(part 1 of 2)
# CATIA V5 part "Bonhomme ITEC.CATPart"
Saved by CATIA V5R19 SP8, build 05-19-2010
Part number: Bonhomme STI 2D
Revision: ANY
Definition: UNKNOWN
Nomenclature: Bonhomme STI 2D
Source: Unknown
Bounding box of the stored display mesh (mm): x -9.149 to 9.622, y -25.063 to 17.35, z -81.288 to -22.199
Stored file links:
  D:\Documents\1_Travail\3 -  Supports d'étude\Bonhomme_ITEC\Activités pédagogiques_Bonhomme ITEC\Activité_4-9.2h_Conception_moule\Activité 4-9.2h_Conception moule silicone\Bonhomme ITEC.CATPart
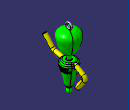
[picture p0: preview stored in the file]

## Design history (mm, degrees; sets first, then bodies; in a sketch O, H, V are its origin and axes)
Set1 "Gravure"
  Sketch1 on yz-plane, origin (0, 0, 0), H (0, 1, 0), V (0, 0, 1)
    polyline C1
    polyline C2
    polyline C3
    polyline C4
    polyline C5
    polyline C6
    polyline C7
    polyline C8
    polyline C9
    polyline C10
  Sketch2 on yz-plane, origin (0, 0, 0), H (0, 1, 0), V (0, 0, 1)
    polyline C1
    polyline C2
    polyline C3
    polyline C4
    polyline C5
    polyline C6
    polyline C7
    polyline C8
    polyline C9
    polyline C10
  Sketch3 on yz-plane, origin (0, 0, 0), H (0, 1, 0), V (0, 0, 1)
    point P1 (-1.9889, -61.7805)
    construction line L1 through (13.4261, 61.6) direction (1, 0)
    construction line L2 through (13.4261, 61.6) direction (0, 1)
    polyline C1
    polyline C2
    polyline C3
    polyline C4
    polyline C5
    polyline C6
    polyline C7
    polyline C8
    polyline C9
    polyline C10
    polyline C11
    polyline C12
    polyline C13
    polyline C14
    polyline C15
    polyline C16
Body1 "Corps" (main body)
  Sketch4 on yz-plane, origin (0, 0, 0), H (0, 1, 0), V (0, 0, 1)
    point P2 (0, -40.025)
    frozenspline C1
    axis line L1 (0, 0) -> (0, -40.025)
    vertical: L1 V
  Shaft1: profile Sketch4, axis Sketch4.L1, angle 360
  Plane1: type OffsetPt, RefPlane xy-plane, RefPoint Sketch4.P2
  Sketch5 on Plane1, origin (0, 0, -40.025), H (1, 0, 0), V (0, 1, 0)
    circle A1 centre (0, 0) radius 4
    radius A1 = 4
  Pad1: profile Sketch5, direction (0, 0, -1), length 10, mirrored extent
  Fillet1: radius 3, on edge [face of Shaft1 from Sketch4.C1 | face of Pad1 from Sketch5.A1]
  Sketch6 on yz-plane, origin (0, 0, 0), H (0, 1, 0), V (0, 0, 1)
    point P1 (0, -50.025)
    line L1 (0, -50.025) -> (11, -50.025)
    line L2 (11, -50.025) -> (15, -54.525)
    point P3 (15, -54.525)
    line L3 (15, -54.525) -> (5.5, -93.6361)
    point P4 (5.5, -93.6361)
    line L4 (5.5, -93.6361) -> (0, -98.525)
    point P5 (0, -98.525)
    axis line L5 (0, -50.025) -> (0, -98.525)
    point P6 (0, -98.525)
    reference intersected line E1 (4, -50.025) -> (-4, -50.025) from end face of Pad1
    length L1 = 11
    distance L5 P3 = 15
    distance P4 L5 = 5.5
    distance P5 L1 = 48.5
    distance P3 L1 = 4.5
    coincidence: P1 V, P5 V, P6 L4, L1 E1
    horizontal: L1 H
    vertical: L5 V
    perpendicularity: L2 L4
  Shaft2: profile Sketch6, axis Sketch6.L5, angle 360
  Sketch7 on yz-plane, origin (0, 0, 0), H (0, 1, 0), V (0, 0, 1)
    arc A1 centre (0, -102.025) radius 4.5 from (0, -106.525) to (0, -97.525) ccw
    point P1 (0, -102.025)
    reference projected point E1 (0, -98.525) from Sketch6.P5
    line L1 (0, -97.525) -> (0, -106.525)
    radius A1 = 4.5
    distance A1 E1 = 1
    coincidence: P1 V, L1 P1
    vertical: L1 V
  Shaft3: profile Sketch7, axis Sketch7.L1, angle 360
  Fillet2: radius 3, on edge [face of Shaft2 from Sketch6.L3 | face of Shaft2 from Sketch6.L4]; edge [face of Shaft2 from Sketch6.L2 | face of Shaft2 from Sketch6.L3]; edge [face of Shaft2 from Sketch6.L1 | face of Shaft2 from Sketch6.L2]
  Fillet3: radius 0.75, on face of Shaft2 from Sketch6.L4
  Sketch8 on zx-plane, origin (0, 0, 0), H (-1, 0, 0), V (0, 0, 1)
    circle A1 centre (0, -54.4777) radius 4
    point P1 (0, -54.4777)
    radius A1 = 4
    coincidence: P1 V
  Sketch9 on yz-plane, origin (0, 0, 0), H (0, 1, 0), V (0, 0, 1)
    point P1 (0, -54.525)
    line L1 (0, -54.525) -> (-10.5, -54.525)
    line L2 (-10.5, -54.525) -> (-27.5165, -50.4397)
    line L3 (-32.8425, -47.1439) -> (-47.3052, -29.9079)
    arc A1 centre (-25.182, -40.716) radius 10 from (-32.8425, -47.1439) to (-27.5165, -50.4397) ccw
    reference projected line E1 through (0, 0) direction (0, 1) from axis of face of Pad1 from Sketch5.A1
    reference projected point E2 (15, -54.525) from vertex [element of Sketch6 | element of Sketch6]
    line L4 (0, -54.525) -> (10.5, -54.525)
    point P7 (11.8397, -54.525)
    line L5 (13, -55.1949) -> (28.1554, -63.9449)
    arc A2 centre (10.5, -59.525) radius 5 from (10.5, -54.525) to (13, -55.1949) cw
    point P8 (32.8809, -66.6731)
    line L6 (29.7512, -71.1429) -> (16.6737, -89.8195)
    arc A3 centre (25.6554, -68.275) radius 5 from (29.7512, -71.1429) to (28.1554, -63.9449) ccw
    point P9 (0, -54.525)
    radius A1 = 10
    length L1 = 10.5
    angle L2 L1 = 13.5
    angle L1 L3 = 50
    length L2 = 17.5
    length L3 = 22.5
    radius A2 = 5
    radius A3 = 5
    angle L5 L6 = 85
    length L4 = 10.5
    length L5 = 17.5
    length L6 = 22.8
    angle L5 L4 = 30
    horizontal: L1 H, L4 H
    tangency: A1 L3, A1 L2, A2 L4, A2 L5, A3 L6, A3 L5
    coincidence: P1 E1, L1 E2, L4 P7, L5 P7, L6 P8, L5 P8, P9 P1
  Rib1: profile Sketch8, centre curve Sketch9
  Fillet4: radius 0.5, on edge [face of Rib1 | face of Rib1] (x2)
  Sketch10 on yz-plane, origin (0, 0, 0), H (0, 1, 0), V (0, 0, 1)
    offset curve E1 from Sketch4.C1
    offset curve E2 from Sketch4.C1
    point P3 (-5.2108, -35)
    line L1 (-5.2108, -35) -> (0, -35)
    point P4 (0, -35)
    line L2 (0, -35) -> (0, -7)
    line L3 (0, -7) -> (-12.8767, -7)
    point P6 (-13.768, -7)
    point P7 (-13.768, -7)
    arc A1 centre (-12.8767, -9) radius 2 from (-12.8767, -7) to (-14.4944, -7.824) ccw
    distance L3 L1 = 28
    distance L3 H = 7
    radius A1 = 2
    coincidence: P3 E1, P4 V, L3 P6, E1 P7, L3 P7, E1 P6
    horizontal: L1 H, L3 H
    vertical: L2 V
    tangency: A1 L3, A1 E1
  Pocket1: profile Sketch10, direction (-1, 0, 0), through (limit type 3)
  Mirror1: of Pocket1, about face of Pocket1 from Sketch10.L2
  Sketch11 on yz-plane, origin (0, 0, 0), H (0, 1, 0), V (0, 0, 1)
    offset curve E1 from Sketch4.C1
    offset curve E2 from Sketch4.C1
    axis line L1 (0, -40.2105) -> (0, 0.6005)
    point P3 (0, -40.2105)
    point P5 (0, -38.5215)
    line L2 (-0.503, -1.4132) -> (0, -1.0375)
    point P6 (0, -1.0375)
    coincidence: P3 V, L1 P5, P6 L1
    vertical: L1 V
  Shaft4: profile Sketch11, axis Sketch11.L1, angle 180
  Sketch12 on yz-plane, origin (0, 0, 0), H (0, 1, 0), V (0, 0, 1)
    point P1 (5, -23.5)
    ellipse A1 centre (5, -23.5) semi-axes 4.5, 2.5 rotation 258.716
    reference intersected line E1 through (0, 0) direction (0, 1) from zx-plane
    reference intersected line E2 (0, -35) -> (-5.2108, -35) from face of Mirror1
    "Radius" A1 = 4.5
    "Radius" A1 = 2.5
    distance P1 E1 = 5
    distance E2 P1 = 11.5
  Pad2: profile Sketch12, direction (-1, 0, 0), up to face of Shaft4 from Sketch11.E2, offset 1.5
  Mirror2: of Pad2, about zx-plane
  Sketch13 on zx-plane, origin (0, 0, 0), H (-1, 0, 0), V (0, 0, 1)
    arc A1 centre (14, -30.9467) radius 3 from (16.7513, -32.1427) to (15.2913, -28.2389) ccw
    point P1 (14, -30.9467)
    line L1 (15.2913, -28.2389) -> (8.1264, -24.8223)
    line L2 (8.1264, -24.8223) -> (6.7159, -27.7804)
    reference projected line E1 through (0, 0) direction (0, 1) from axis of face of Pad1 from Sketch5.A1
    reference projected line E2 (-6.0494, -38.9467) -> (6.0494, -38.9467) from edge [face of Fillet1 | face of Shaft1 from Sketch4.C1]
    axis line L3 (20.0017, -33.5557) -> (2.8816, -26.1136)
    point P6 (16.7513, -32.1427)
    point P7 (6.7159, -27.7804)
    radius A1 = 3
    distance P1 E1 = 14
    distance E2 P1 = 8
    angle L3 L1 = 2
    tangency: L1 A1
    perpendicularity: L2 L1
    coincidence: L3 P1, L3 P6, L3 P7
  Shaft5: profile Sketch13, axis Sketch13.L3, angle 360
  Fillet5: radius 0.5, on face of Mirror2; end face of Pad2
  Fillet6: radius 0.75, on edge [face of Shaft2 from Sketch6.L2 | face of Rib1]; edge [face of Rib1 | face of Shaft2 from Sketch6.L2]
  Fillet7: radius 0.75, on face of Shaft4 from Sketch11.E2
  Fillet8: radius 0.5, on edge [face of Shaft1 from Sketch4.C1 | face of Mirror1]
  Sketch14 on yz-plane, origin (0, 0, 0), H (0, 1, 0), V (0, 0, 1)
    line L1 (0.9195, -63.8789) -> (0.9195, -59.1378)
    line L2 (0.9195, -59.1378) -> (0.9178, -59.0657)
    line L3 (0.9178, -59.0657) -> (0.9128, -58.9974)
    line L4 (0.9128, -58.9974) -> (0.9043, -58.9327)
    line L5 (0.9043, -58.9327) -> (0.8926, -58.8718)
    line L6 (0.8926, -58.8718) -> (0.8774, -58.8145)
    line L7 (0.8774, -58.8145) -> (0.8589, -58.7609)
    line L8 (0.8589, -58.7609) -> (0.837, -58.7111)
    line L9 (0.837, -58.7111) -> (0.8118, -58.6649)
    line L10 (0.8118, -58.6649) -> (0.7832, -58.6224)
    line L11 (0.7832, -58.6224) -> (0.7512, -58.5836)
    line L12 (0.7512, -58.5836) -> (0.7165, -58.5485)
    line L13 (0.7165, -58.5485) -> (0.6799, -58.5171)
    line L14 (0.6799, -58.5171) -> (0.6413, -58.4894)
    line L15 (0.6413, -58.4894) -> (0.6008, -58.4654)
    line L16 (0.6008, -58.4654) -> (0.5582, -58.4451)
    line L17 (0.5582, -58.4451) -> (0.5138, -58.4284)
    line L18 (0.5138, -58.4284) -> (0.4673, -58.4155)
    line L19 (0.4673, -58.4155) -> (0.4188, -58.4063)
    line L20 (0.4188, -58.4063) -> (0.3684, -58.4007)
    line L21 (0.3684, -58.4007) -> (0.3161, -58.3989)
    line L22 (0.3161, -58.3989) -> (0.2621, -58.4007)
    line L23 (0.2621, -58.4007) -> (0.2102, -58.4062)
    line L24 (0.2102, -58.4062) -> (0.1605, -58.4153)
    line L25 (0.1605, -58.4153) -> (0.1128, -58.4281)
    line L26 (0.1128, -58.4281) -> (0.0672, -58.4446)
    line L27 (0.0672, -58.4446) -> (0.0237, -58.4646)
    line L28 (0.0237, -58.4646) -> (-0.0177, -58.4884)
    line L29 (-0.0177, -58.4884) -> (-0.057, -58.5158)
    line L30 (-0.057, -58.5158) -> (-0.0942, -58.5468)
    line L31 (-0.0942, -58.5468) -> (-0.1293, -58.5816)
    line L32 (-0.1293, -58.5816) -> (-0.1617, -58.62)
    line L33 (-0.1617, -58.62) -> (-0.1906, -58.6622)
    line L34 (-0.1906, -58.6622) -> (-0.2162, -58.7083)
    line L35 (-0.2162, -58.7083) -> (-0.2384, -58.7582)
    line L36 (-0.2384, -58.7582) -> (-0.2571, -58.8119)
    line L37 (-0.2571, -58.8119) -> (-0.2724, -58.8695)
    line L38 (-0.2724, -58.8695) -> (-0.2843, -58.9308)
    line L39 (-0.2843, -58.9308) -> (-0.2929, -58.996)
    line L40 (-0.2929, -58.996) -> (-0.298, -59.065)
    line L41 (-0.298, -59.065) -> (-0.2997, -59.1378)
    line L42 (-0.2997, -59.1378) -> (-0.2997, -63.8789)
    line L43 (-0.2997, -63.8789) -> (-0.298, -63.9517)
    line L44 (-0.298, -63.9517) -> (-0.2929, -64.0208)
    line L45 (-0.2929, -64.0208) -> (-0.2843, -64.086)
    line L46 (-0.2843, -64.086) -> (-0.2724, -64.1475)
    line L47 (-0.2724, -64.1475) -> (-0.2571, -64.2052)
    line L48 (-0.2571, -64.2052) -> (-0.2384, -64.2592)
    line L49 (-0.2384, -64.2592) -> (-0.2162, -64.3093)
    line L50 (-0.2162, -64.3093) -> (-0.1906, -64.3557)
    line L51 (-0.1906, -64.3557) -> (-0.1617, -64.3983)
    line L52 (-0.1617, -64.3983) -> (-0.1293, -64.4372)
    line L53 (-0.1293, -64.4372) -> (-0.0942, -64.4723)
    line L54 (-0.0942, -64.4723) -> (-0.057, -64.5037)
    line L55 (-0.057, -64.5037) -> (-0.0177, -64.5314)
    line L56 (-0.0177, -64.5314) -> (0.0237, -64.5554)
    line L57 (0.0237, -64.5554) -> (0.0672, -64.5757)
    line L58 (0.0672, -64.5757) -> (0.1128, -64.5923)
    line L59 (0.1128, -64.5923) -> (0.1605, -64.6053)
    line L60 (0.1605, -64.6053) -> (0.2102, -64.6145)
    line L61 (0.2102, -64.6145) -> (0.2621, -64.62)
    line L62 (0.2621, -64.62) -> (0.3161, -64.6219)
    line L63 (0.3161, -64.6219) -> (0.3677, -64.62)
    line L64 (0.3677, -64.62) -> (0.4175, -64.6144)
    line L65 (0.4175, -64.6144) -> (0.4654, -64.6051)
    line L66 (0.4654, -64.6051) -> (0.5115, -64.592)
    line L67 (0.5115, -64.592) -> (0.5557, -64.5752)
    line L68 (0.5557, -64.5752) -> (0.5981, -64.5546)
    line L69 (0.5981, -64.5546) -> (0.6386, -64.5304)
    line L70 (0.6386, -64.5304) -> (0.6773, -64.5024)
    line L71 (0.6773, -64.5024) -> (0.7141, -64.4706)
    line L72 (0.7141, -64.4706) -> (0.7491, -64.4351)
    line L73 (0.7491, -64.4351) -> (0.7815, -64.3959)
    line L74 (0.7815, -64.3959) -> (0.8105, -64.3531)
    line L75 (0.8105, -64.3531) -> (0.836, -64.3066)
    line L76 (0.836, -64.3066) -> (0.8582, -64.2565)
    line L77 (0.8582, -64.2565) -> (0.8769, -64.2027)
    line L78 (0.8769, -64.2027) -> (0.8922, -64.1452)
    line L79 (0.8922, -64.1452) -> (0.9042, -64.0841)
    line L80 (0.9042, -64.0841) -> (0.9127, -64.0194)
    line L81 (0.9127, -64.0194) -> (0.9178, -63.951)
    line L82 (0.9178, -63.951) -> (0.9195, -63.8789)
    line L83 (-2.8078, -62.202) -> (-2.8931, -62.124)
    line L84 (-2.8931, -62.124) -> (-2.9734, -62.0514)
    line L85 (-2.9734, -62.0514) -> (-3.0487, -61.9844)
    line L86 (-3.0487, -61.9844) -> (-3.1191, -61.9229)
    line L87 (-3.1191, -61.9229) -> (-3.1844, -61.867)
    line L88 (-3.1844, -61.867) -> (-3.2447, -61.8166)
    line L89 (-3.2447, -61.8166) -> (-3.3, -61.7718)
    line L90 (-3.3, -61.7718) -> (-3.3503, -61.7325)
    line L91 (-3.3503, -61.7325) -> (-3.3955, -61.6987)
    line L92 (-3.3955, -61.6987) -> (-3.4358, -61.6705)
    line L93 (-3.4358, -61.6705) -> (-3.502, -61.6228)
    line L94 (-3.502, -61.6228) -> (-3.5659, -61.5752)
    line L95 (-3.5659, -61.5752) -> (-3.6276, -61.5274)
    line L96 (-3.6276, -61.5274) -> (-3.687, -61.4797)
    line L97 (-3.687, -61.4797) -> (-3.7442, -61.4319)
    line L98 (-3.7442, -61.4319) -> (-3.7991, -61.384)
    line L99 (-3.7991, -61.384) -> (-3.8517, -61.3362)
    line L100 (-3.8517, -61.3362) -> (-3.9021, -61.2882)
    line L101 (-3.9021, -61.2882) -> (-3.9502, -61.2403)
    line L102 (-3.9502, -61.2403) -> (-3.9961, -61.1923)
    line L103 (-3.9961, -61.1923) -> (-4.0398, -61.1441)
    line L104 (-4.0398, -61.1441) -> (-4.0813, -61.0957)
    line L105 (-4.0813, -61.0957) -> (-4.1207, -61.0471)
    line L106 (-4.1207, -61.0471) -> (-4.158, -60.9982)
    line L107 (-4.158, -60.9982) -> (-4.1932, -60.949)
    line L108 (-4.1932, -60.949) -> (-4.2262, -60.8997)
    line L109 (-4.2262, -60.8997) -> (-4.257, -60.85)
    line L110 (-4.257, -60.85) -> (-4.2858, -60.8002)
    line L111 (-4.2858, -60.8002) -> (-4.3124, -60.75)
    line L112 (-4.3124, -60.75) -> (-4.3368, -60.6997)
    line L113 (-4.3368, -60.6997) -> (-4.3591, -60.6493)
    line L114 (-4.3591, -60.6493) -> (-4.3789, -60.5991)
    line L115 (-4.3789, -60.5991) -> (-4.3965, -60.5491)
    line L116 (-4.3965, -60.5491) -> (-4.4117, -60.4994)
    line L117 (-4.4117, -60.4994) -> (-4.4246, -60.4498)
    line L118 (-4.4246, -60.4498) -> (-4.4351, -60.4004)
    line L119 (-4.4351, -60.4004) -> (-4.4433, -60.3513)
    line L120 (-4.4433, -60.3513) -> (-4.4491, -60.3023)
    line L121 (-4.4491, -60.3023) -> (-4.4526, -60.2536)
    line L122 (-4.4526, -60.2536) -> (-4.4538, -60.205)
    line L123 (-4.4538, -60.205) -> (-4.4526, -60.153)
    line L124 (-4.4526, -60.153) -> (-4.4488, -60.1022)
    line L125 (-4.4488, -60.1022) -> (-4.4425, -60.0524)
    line L126 (-4.4425, -60.0524) -> (-4.4338, -60.0037)
    line L127 (-4.4338, -60.0037) -> (-4.4225, -59.9562)
    line L128 (-4.4225, -59.9562) -> (-4.4087, -59.9097)
    line L129 (-4.4087, -59.9097) -> (-4.3925, -59.8644)
    line L130 (-4.3925, -59.8644) -> (-4.3737, -59.8202)
    line L131 (-4.3737, -59.8202) -> (-4.3524, -59.777)
    line L132 (-4.3524, -59.777) -> (-4.3286, -59.735)
    line L133 (-4.3286, -59.735) -> (-4.3027, -59.6945)
    line L134 (-4.3027, -59.6945) -> (-4.2749, -59.6558)
    line L135 (-4.2749, -59.6558) -> (-4.2454, -59.619)
    line L136 (-4.2454, -59.619) -> (-4.214, -59.584)
    line L137 (-4.214, -59.584) -> (-4.1808, -59.5508)
    line L138 (-4.1808, -59.5508) -> (-4.1459, -59.5195)
    line L139 (-4.1459, -59.5195) -> (-4.1091, -59.4901)
    line L140 (-4.1091, -59.4901) -> (-4.0705, -59.4624)
    line L141 (-4.0705, -59.4624) -> (-4.0301, -59.4367)
    line L142 (-4.0301, -59.4367) -> (-3.9879, -59.4128)
    line L143 (-3.9879, -59.4128) -> (-3.9444, -59.391)
    line L144 (-3.9444, -59.391) -> (-3.9001, -59.3714)
    line L145 (-3.9001, -59.3714) -> (-3.8551, -59.3542)
    line L146 (-3.8551, -59.3542) -> (-3.8093, -59.3392)
    line L147 (-3.8093, -59.3392) -> (-3.7626, -59.3266)
    line L148 (-3.7626, -59.3266) -> (-3.7153, -59.3162)
    line L149 (-3.7153, -59.3162) -> (-3.6671, -59.3082)
    line L150 (-3.6671, -59.3082) -> (-3.6181, -59.3024)
    line L151 (-3.6181, -59.3024) -> (-3.5684, -59.299)
    line L152 (-3.5684, -59.299) -> (-3.5179, -59.2979)
    line L153 (-3.5179, -59.2979) -> (-3.4126, -59.3026)
    line L154 (-3.4126, -59.3026) -> (-3.312, -59.3167)
    line L155 (-3.312, -59.3167) -> (-3.2159, -59.3403)
    line L156 (-3.2159, -59.3403) -> (-3.1245, -59.3734)
    line L157 (-3.1245, -59.3734) -> (-3.0376, -59.4159)
    line L158 (-3.0376, -59.4159) -> (-2.9554, -59.4678)
    line L159 (-2.9554, -59.4678) -> (-2.8777, -59.5292)
    line L160 (-2.8777, -59.5292) -> (-2.8046, -59.6)
    line L161 (-2.8046, -59.6) -> (-2.7362, -59.6802)
    line L162 (-2.7362, -59.6802) -> (-2.6723, -59.7699)
    line L163 (-2.6723, -59.7699) -> (-2.6635, -59.7844)
    line L164 (-2.6635, -59.7844) -> (-2.6537, -59.8031)
    line L165 (-2.6537, -59.8031) -> (-2.6427, -59.8261)
    line L166 (-2.6427, -59.8261) -> (-2.6306, -59.8533)
    line L167 (-2.6306, -59.8533) -> (-2.6174, -59.8848)
    line L168 (-2.6174, -59.8848) -> (-2.6031, -59.9206)
    line L169 (-2.6031, -59.9206) -> (-2.5877, -59.9607)
    line L170 (-2.5877, -59.9607) -> (-2.5711, -60.005)
    line L171 (-2.5711, -60.005) -> (-2.5535, -60.0536)
    line L172 (-2.5535, -60.0536) -> (-2.5348, -60.1065)
    line L173 (-2.5348, -60.1065) -> (-2.5152, -60.1602)
    line L174 (-2.5152, -60.1602) -> (-2.4952, -60.2114)
    line L175 (-2.4952, -60.2114) -> (-2.4747, -60.2601)
    line L176 (-2.4747, -60.2601) -> (-2.4537, -60.3062)
    line L177 (-2.4537, -60.3062) -> (-2.4322, -60.3497)
    line L178 (-2.4322, -60.3497) -> (-2.4102, -60.3907)
    line L179 (-2.4102, -60.3907) -> (-2.3877, -60.4292)
    line L180 (-2.3877, -60.4292) -> (-2.3647, -60.4651)
    line L181 (-2.3647, -60.4651) -> (-2.3412, -60.4985)
    line L182 (-2.3412, -60.4985) -> (-2.3172, -60.5293)
    line L183 (-2.3172, -60.5293) -> (-2.2919, -60.5574)
    line L184 (-2.2919, -60.5574) -> (-2.2643, -60.5825)
    line L185 (-2.2643, -60.5825) -> (-2.2344, -60.6047)
    line L186 (-2.2344, -60.6047) -> (-2.2023, -60.6239)
    line L187 (-2.2023, -60.6239) -> (-2.1679, -60.6401)
    line L188 (-2.1679, -60.6401) -> (-2.1313, -60.6534)
    line L189 (-2.1313, -60.6534) -> (-2.0924, -60.6638)
    line L190 (-2.0924, -60.6638) -> (-2.0512, -60.6712)
    line L191 (-2.0512, -60.6712) -> (-2.0078, -60.6756)
    line L192 (-2.0078, -60.6756) -> (-1.9621, -60.6771)
    line L193 (-1.9621, -60.6771) -> (-1.9218, -60.6757)
    line L194 (-1.9218, -60.6757) -> (-1.8828, -60.6717)
    line L195 (-1.8828, -60.6717) -> (-1.8453, -60.6649)
    line L196 (-1.8453, -60.6649) -> (-1.8091, -60.6554)
    line L197 (-1.8091, -60.6554) -> (-1.7744, -60.6432)
    line L198 (-1.7744, -60.6432) -> (-1.741, -60.6283)
    line L199 (-1.741, -60.6283) -> (-1.709, -60.6107)
    line L200 (-1.709, -60.6107) -> (-1.6784, -60.5904)
    line L201 (-1.6784, -60.5904) -> (-1.6492, -60.5674)
    line L202 (-1.6492, -60.5674) -> (-1.6214, -60.5416)
    line L203 (-1.6214, -60.5416) -> (-1.5957, -60.5136)
    line L204 (-1.5957, -60.5136) -> (-1.5727, -60.4835)
    line L205 (-1.5727, -60.4835) -> (-1.5524, -60.4515)
    line L206 (-1.5524, -60.4515) -> (-1.5348, -60.4175)
    line L207 (-1.5348, -60.4175) -> (-1.5198, -60.3815)
    line L208 (-1.5198, -60.3815) -> (-1.5077, -60.3436)
    line L209 (-1.5077, -60.3436) -> (-1.4982, -60.3037)
    line L210 (-1.4982, -60.3037) -> (-1.4914, -60.2618)
    line L211 (-1.4914, -60.2618) -> (-1.4873, -60.218)
    line L212 (-1.4873, -60.218) -> (-1.486, -60.1722)
    line L213 (-1.486, -60.1722) -> (-1.4873, -60.1153)
    line L214 (-1.4873, -60.1153) -> (-1.4911, -60.0579)
    line L215 (-1.4911, -60.0579) -> (-1.4974, -60)
    line L216 (-1.4974, -60) -> (-1.5063, -59.9416)
    line L217 (-1.5063, -59.9416) -> (-1.5178, -59.8828)
    line L218 (-1.5178, -59.8828) -> (-1.5318, -59.8234)
    line L219 (-1.5318, -59.8234) -> (-1.5483, -59.7636)
    line L220 (-1.5483, -59.7636) -> (-1.5674, -59.7033)
    line L221 (-1.5674, -59.7033) -> (-1.5891, -59.6424)
    line L222 (-1.5891, -59.6424) -> (-1.6132, -59.5811)
    line L223 (-1.6132, -59.5811) -> (-1.6399, -59.5201)
    line L224 (-1.6399, -59.5201) -> (-1.6691, -59.4603)
    line L225 (-1.6691, -59.4603) -> (-1.7009, -59.4015)
    line L226 (-1.7009, -59.4015) -> (-1.7351, -59.344)
    line L227 (-1.7351, -59.344) -> (-1.7718, -59.2876)
    line L228 (-1.7718, -59.2876) -> (-1.811, -59.2323)
    line L229 (-1.811, -59.2323) -> (-1.8527, -59.1782)
    line L230 (-1.8527, -59.1782) -> (-1.897, -59.1253)
    line L231 (-1.897, -59.1253) -> (-1.9437, -59.0735)
    line L232 (-1.9437, -59.0735) -> (-1.9929, -59.0228)
    line L233 (-1.9929, -59.0228) -> (-2.0448, -58.9737)
    line L234 (-2.0448, -58.9737) -> (-2.0993, -58.9265)
    line L235 (-2.0993, -58.9265) -> (-2.1566, -58.8813)
    line L236 (-2.1566, -58.8813) -> (-2.2166, -58.8379)
    line L237 (-2.2166, -58.8379) -> (-2.2793, -58.7965)
    line L238 (-2.2793, -58.7965) -> (-2.3446, -58.7571)
    line L239 (-2.3446, -58.7571) -> (-2.4127, -58.7195)
    line L240 (-2.4127, -58.7195) -> (-2.4835, -58.6839)
    line L241 (-2.4835, -58.6839) -> (-2.5571, -58.6503)
    line L242 (-2.5571, -58.6503) -> (-2.6333, -58.6185)
    line L243 (-2.6333, -58.6185) -> (-2.7122, -58.5892)
    line L244 (-2.7122, -58.5892) -> (-2.7938, -58.5631)
    line L245 (-2.7938, -58.5631) -> (-2.878, -58.54)
    line L246 (-2.878, -58.54) -> (-2.965, -58.52)
    line L247 (-2.965, -58.52) -> (-3.0546, -58.503)
    line L248 (-3.0546, -58.503) -> (-3.1468, -58.4892)
    line L249 (-3.1468, -58.4892) -> (-3.2417, -58.4784)
    line L250 (-3.2417, -58.4784) -> (-3.3393, -58.4707)
    line L251 (-3.3393, -58.4707) -> (-3.4396, -58.4661)
    line L252 (-3.4396, -58.4661) -> (-3.5425, -58.4645)
    line L253 (-3.5425, -58.4645) -> (-3.6663, -58.4665)
    line L254 (-3.6663, -58.4665) -> (-3.7864, -58.4724)
    line L255 (-3.7864, -58.4724) -> (-3.9027, -58.4823)
    line L256 (-3.9027, -58.4823) -> (-4.0154, -58.4961)
    line L257 (-4.0154, -58.4961) -> (-4.1244, -58.5138)
    line L258 (-4.1244, -58.5138) -> (-4.2297, -58.5355)
    line L259 (-4.2297, -58.5355) -> (-4.3313, -58.5611)
    line L260 (-4.3313, -58.5611) -> (-4.4292, -58.5906)
    line L261 (-4.4292, -58.5906) -> (-4.5234, -58.6242)
    line L262 (-4.5234, -58.6242) -> (-4.6139, -58.6616)
    line L263 (-4.6139, -58.6616) -> (-4.6707, -58.6889)
    line L264 (-4.6707, -58.6889) -> (-4.7261, -58.7181)
    line L265 (-4.7261, -58.7181) -> (-4.78, -58.7493)
    line L266 (-4.78, -58.7493) -> (-4.8326, -58.7824)
    line L267 (-4.8326, -58.7824) -> (-4.8838, -58.8176)
    line L268 (-4.8838, -58.8176) -> (-4.9336, -58.8547)
    line L269 (-4.9336, -58.8547) -> (-4.982, -58.8938)
    line L270 (-4.982, -58.8938) -> (-5.029, -58.9348)
    line L271 (-5.029, -58.9348) -> (-5.0746, -58.9778)
    line L272 (-5.0746, -58.9778) -> (-5.1188, -59.0228)
    line L273 (-5.1188, -59.0228) -> (-5.1614, -59.0695)
    line L274 (-5.1614, -59.0695) -> (-5.202, -59.1177)
    line L275 (-5.202, -59.1177) -> (-5.2407, -59.1672)
    line L276 (-5.2407, -59.1672) -> (-5.2774, -59.2182)
    line L277 (-5.2774, -59.2182) -> (-5.3122, -59.2707)
    line L278 (-5.3122, -59.2707) -> (-5.3452, -59.3245)
    line L279 (-5.3452, -59.3245) -> (-5.3761, -59.3798)
    line L280 (-5.3761, -59.3798) -> (-5.4052, -59.4366)
    line L281 (-5.4052, -59.4366) -> (-5.4323, -59.4948)
    line L282 (-5.4323, -59.4948) -> (-5.4575, -59.5544)
    line L283 (-5.4575, -59.5544) -> (-5.4805, -59.615)
    line L284 (-5.4805, -59.615) -> (-5.5011, -59.676)
    line L285 (-5.5011, -59.676) -> (-5.5192, -59.7375)
    line L286 (-5.5192, -59.7375) -> (-5.535, -59.7994)
    line L287 (-5.535, -59.7994) -> (-5.5483, -59.8618)
    line L288 (-5.5483, -59.8618) -> (-5.5592, -59.9246)
    line L289 (-5.5592, -59.9246) -> (-5.5676, -59.9878)
    line L290 (-5.5676, -59.9878) -> (-5.5737, -60.0516)
    line L291 (-5.5737, -60.0516) -> (-5.5773, -60.1158)
    line L292 (-5.5773, -60.1158) -> (-5.5786, -60.1804)
    line L293 (-5.5786, -60.1804) -> (-5.576, -60.2813)
    line L294 (-5.576, -60.2813) -> (-5.5684, -60.3803)
    line L295 (-5.5684, -60.3803) -> (-5.5558, -60.4775)
    line L296 (-5.5558, -60.4775) -> (-5.5382, -60.5728)
    line L297 (-5.5382, -60.5728) -> (-5.5154, -60.6663)
    line L298 (-5.5154, -60.6663) -> (-5.4877, -60.758)
    line L299 (-5.4877, -60.758) -> (-5.4548, -60.8477)
    line L300 (-5.4548, -60.8477) -> (-5.417, -60.9357)
    line L301 (-5.417, -60.9357) -> (-5.3741, -61.0218)
    line L302 (-5.3741, -61.0218) -> (-5.3261, -61.106)
    line L303 (-5.3261, -61.106) -> (-5.2755, -61.1876)
    line L304 (-5.2755, -61.1876) -> (-5.2247, -61.2655)
    line L305 (-5.2247, -61.2655) -> (-5.1737, -61.3398)
    line L306 (-5.1737, -61.3398) -> (-5.1225, -61.4105)
    line L307 (-5.1225, -61.4105) -> (-5.0711, -61.4775)
    line L308 (-5.0711, -61.4775) -> (-5.0195, -61.541)
    line L309 (-5.0195, -61.541) -> (-4.9676, -61.6008)
    line L310 (-4.9676, -61.6008) -> (-4.9156, -61.6571)
    line L311 (-4.9156, -61.6571) -> (-4.8634, -61.7097)
    line L312 (-4.8634, -61.7097) -> (-4.8109, -61.7587)
    line L313 (-4.8109, -61.7587) -> (-4.7548, -61.8086)
    line L314 (-4.7548, -61.8086) -> (-4.6917, -61.8639)
    line L315 (-4.6917, -61.8639) -> (-4.6214, -61.9245)
    line L316 (-4.6214, -61.9245) -> (-4.544, -61.9906)
    line L317 (-4.544, -61.9906) -> (-4.4595, -62.062)
    line L318 (-4.4595, -62.062) -> (-4.3679, -62.1388)
    line L319 (-4.3679, -62.1388) -> (-4.2692, -62.2209)
    line L320 (-4.2692, -62.2209) -> (-4.1633, -62.3085)
    line L321 (-4.1633, -62.3085) -> (-4.0504, -62.4014)
    line L322 (-4.0504, -62.4014) -> (-3.9304, -62.4997)
    line L323 (-3.9304, -62.4997) -> (-3.8108, -62.5984)
    line L324 (-3.8108, -62.5984) -> (-3.6988, -62.6926)
    line L325 (-3.6988, -62.6926) -> (-3.5947, -62.7823)
    line L326 (-3.5947, -62.7823) -> (-3.4983, -62.8674)
    line L327 (-3.4983, -62.8674) -> (-3.4096, -62.9481)
    line L328 (-3.4096, -62.9481) -> (-3.3287, -63.0243)
    line L329 (-3.3287, -63.0243) -> (-3.2556, -63.0959)
    line L330 (-3.2556, -63.0959) -> (-3.1902, -63.163)
    line L331 (-3.1902, -63.163) -> (-3.1326, -63.2256)
    line L332 (-3.1326, -63.2256) -> (-3.0828, -63.2837)
    line L333 (-3.0828, -63.2837) -> (-3.063, -63.3063)
    line L334 (-3.063, -63.3063) -> (-3.0432, -63.3298)
    line L335 (-3.0432, -63.3298) -> (-3.0233, -63.3543)
    line L336 (-3.0233, -63.3543) -> (-3.0033, -63.3796)
    line L337 (-3.0033, -63.3796) -> (-2.9832, -63.4058)
    line L338 (-2.9832, -63.4058) -> (-2.9631, -63.4329)
    line L339 (-2.9631, -63.4329) -> (-2.9428, -63.461)
    line L340 (-2.9428, -63.461) -> (-2.9225, -63.4899)
    line L341 (-2.9225, -63.4899) -> (-2.9021, -63.5198)
    line L342 (-2.9021, -63.5198) -> (-2.8816, -63.5505)
    line L343 (-2.8816, -63.5505) -> (-5.0244, -63.5505)
    line L344 (-5.0244, -63.5505) -> (-5.0869, -63.5518)
    line L345 (-5.0869, -63.5518) -> (-5.1464, -63.5558)
    line L346 (-5.1464, -63.5558) -> (-5.2028, -63.5623)
    line L347 (-5.2028, -63.5623) -> (-5.2562, -63.5715)
    line L348 (-5.2562, -63.5715) -> (-5.3066, -63.5834)
    line L349 (-5.3066, -63.5834) -> (-5.3539, -63.5978)
    line L350 (-5.3539, -63.5978) -> (-5.3982, -63.6149)
    line L351 (-5.3982, -63.6149) -> (-5.4395, -63.6346)
    line L352 (-5.4395, -63.6346) -> (-5.4777, -63.6569)
    line L353 (-5.4777, -63.6569) -> (-5.5129, -63.6819)
    line L354 (-5.5129, -63.6819) -> (-5.5448, -63.7091)
    line L355 (-5.5448, -63.7091) -> (-5.5735, -63.7382)
    line L356 (-5.5735, -63.7382) -> (-5.5987, -63.7692)
    line L357 (-5.5987, -63.7692) -> (-5.6206, -63.802)
    line L358 (-5.6206, -63.802) -> (-5.6391, -63.8368)
    line L359 (-5.6391, -63.8368) -> (-5.6542, -63.8735)
    line L360 (-5.6542, -63.8735) -> (-5.666, -63.912)
    line L361 (-5.666, -63.912) -> (-5.6744, -63.9525)
    line L362 (-5.6744, -63.9525) -> (-5.6795, -63.9948)
    line L363 (-5.6795, -63.9948) -> (-5.6812, -64.039)
    line L364 (-5.6812, -64.039) -> (-5.6798, -64.0786)
    line L365 (-5.6798, -64.0786) -> (-5.6758, -64.117)
    line L366 (-5.6758, -64.117) -> (-5.6692, -64.1541)
    line L367 (-5.6692, -64.1541) -> (-5.6598, -64.19)
    line L368 (-5.6598, -64.19) -> (-5.6478, -64.2247)
    line L369 (-5.6478, -64.2247) -> (-5.6331, -64.2582)
    line L370 (-5.6331, -64.2582) -> (-5.6158, -64.2904)
    line L371 (-5.6158, -64.2904) -> (-5.5958, -64.3214)
    line L372 (-5.5958, -64.3214) -> (-5.5731, -64.3512)
    line L373 (-5.5731, -64.3512) -> (-5.5478, -64.3797)
    line L374 (-5.5478, -64.3797) -> (-5.5197, -64.4062)
    line L375 (-5.5197, -64.4062) -> (-5.4889, -64.4299)
    line L376 (-5.4889, -64.4299) -> (-5.4553, -64.4509)
    line L377 (-5.4553, -64.4509) -> (-5.419, -64.469)
    line L378 (-5.419, -64.469) -> (-5.38, -64.4844)
    line L379 (-5.38, -64.4844) -> (-5.3382, -64.4969)
    line L380 (-5.3382, -64.4969) -> (-5.2936, -64.5067)
    line L381 (-5.2936, -64.5067) -> (-5.2463, -64.5137)
    line L382 (-5.2463, -64.5137) -> (-5.1962, -64.5179)
    line L383 (-5.1962, -64.5179) -> (-5.1434, -64.5193)
    line L384 (-5.1434, -64.5193) -> (-2.1222, -64.5193)
    line L385 (-2.1222, -64.5193) -> (-2.062, -64.5175)
    line L386 (-2.062, -64.5175) -> (-2.0045, -64.5125)
    line L387 (-2.0045, -64.5125) -> (-1.9497, -64.5039)
    line L388 (-1.9497, -64.5039) -> (-1.8976, -64.492)
    line L389 (-1.8976, -64.492) -> (-1.8482, -64.4767)
    line L390 (-1.8482, -64.4767) -> (-1.8016, -64.4579)
    line L391 (-1.8016, -64.4579) -> (-1.7576, -64.4358)
    line L392 (-1.7576, -64.4358) -> (-1.7163, -64.4102)
    line L393 (-1.7163, -64.4102) -> (-1.6778, -64.3813)
    line L394 (-1.6778, -64.3813) -> (-1.642, -64.3489)
    line L395 (-1.642, -64.3489) -> (-1.6092, -64.3142)
    line L396 (-1.6092, -64.3142) -> (-1.5799, -64.2784)
    line L397 (-1.5799, -64.2784) -> (-1.554, -64.2413)
    line L398 (-1.554, -64.2413) -> (-1.5316, -64.2031)
    line L399 (-1.5316, -64.2031) -> (-1.5127, -64.1637)
    line L400 (-1.5127, -64.1637) -> (-1.4971, -64.1231)
    line L401 (-1.4971, -64.1231) -> (-1.4851, -64.0812)
    line L402 (-1.4851, -64.0812) -> (-1.4765, -64.0382)
    line L403 (-1.4765, -64.0382) -> (-1.4713, -63.994)
    line L404 (-1.4713, -63.994) -> (-1.4696, -63.9487)
    line L405 (-1.4696, -63.9487) -> (-1.4707, -63.9182)
    line L406 (-1.4707, -63.9182) -> (-1.474, -63.8857)
    line L407 (-1.474, -63.8857) -> (-1.4795, -63.8513)
    line L408 (-1.4795, -63.8513) -> (-1.4873, -63.815)
    line L409 (-1.4873, -63.815) -> (-1.4973, -63.7768)
    line L410 (-1.4973, -63.7768) -> (-1.5095, -63.7366)
    line L411 (-1.5095, -63.7366) -> (-1.5239, -63.6945)
    line L412 (-1.5239, -63.6945) -> (-1.5405, -63.6505)
    line L413 (-1.5405, -63.6505) -> (-1.5593, -63.6045)
    line L414 (-1.5593, -63.6045) -> (-1.5804, -63.5567)
    line L415 (-1.5804, -63.5567) -> (-1.6028, -63.5089)
    line L416 (-1.6028, -63.5089) -> (-1.6255, -63.4632)
    line L417 (-1.6255, -63.4632) -> (-1.6487, -63.4195)
    line L418 (-1.6487, -63.4195) -> (-1.6723, -63.378)
    line L419 (-1.6723, -63.378) -> (-1.6964, -63.3386)
    line L420 (-1.6964, -63.3386) -> (-1.7208, -63.3013)
    line L421 (-1.7208, -63.3013) -> (-1.7456, -63.266)
    line L422 (-1.7456, -63.266) -> (-1.7709, -63.2329)
    line L423 (-1.7709, -63.2329) -> (-1.7965, -63.2018)
    line L424 (-1.7965, -63.2018) -> (-1.8226, -63.1728)
    line L425 (-1.8226, -63.1728) -> (-1.9307, -63.0612)
    line L426 (-1.9307, -63.0612) -> (-2.0367, -62.9528)
    line L427 (-2.0367, -62.9528) -> (-2.1406, -62.8476)
    line L428 (-2.1406, -62.8476) -> (-2.2423, -62.7456)
    line L429 (-2.2423, -62.7456) -> (-2.3418, -62.6469)
    line L430 (-2.3418, -62.6469) -> (-2.4393, -62.5515)
    line L431 (-2.4393, -62.5515) -> (-2.5346, -62.4592)
    line L432 (-2.5346, -62.4592) -> (-2.6278, -62.3703)
    line L433 (-2.6278, -62.3703) -> (-2.7188, -62.2846)
    line L434 (-2.7188, -62.2846) -> (-2.8078, -62.202)
    line L435 (4.8602, -63.8789) -> (4.8602, -59.5072)
    line L436 (4.8602, -59.5072) -> (6.1901, -59.5072)
    line L437 (6.1901, -59.5072) -> (6.2509, -59.5058)
    line L438 (6.2509, -59.5058) -> (6.3085, -59.5017)
    line L439 (6.3085, -59.5017) -> (6.3629, -59.4948)
    line L440 (6.3629, -59.4948) -> (6.4141, -59.4852)
    line L441 (6.4141, -59.4852) -> (6.4621, -59.4728)
    line L442 (6.4621, -59.4728) -> (6.5069, -59.4577)
    line L443 (6.5069, -59.4577) -> (6.5485, -59.4398)
    line L444 (6.5485, -59.4398) -> (6.5868, -59.4192)
    line L445 (6.5868, -59.4192) -> (6.622, -59.3958)
    line L446 (6.622, -59.3958) -> (6.654, -59.3697)
    line L447 (6.654, -59.3697) -> (6.6829, -59.3413)
    line L448 (6.6829, -59.3413) -> (6.7087, -59.3111)
    line L449 (6.7087, -59.3111) -> (6.7315, -59.2792)
    line L450 (6.7315, -59.2792) -> (6.7512, -59.2455)
    line L451 (6.7512, -59.2455) -> (6.7679, -59.2101)
    line L452 (6.7679, -59.2101) -> (6.7816, -59.1729)
    line L453 (6.7816, -59.1729) -> (6.7922, -59.1339)
    line L454 (6.7922, -59.1339) -> (6.7998, -59.0932)
    line L455 (6.7998, -59.0932) -> (6.8044, -59.0507)
    line L456 (6.8044, -59.0507) -> (6.8059, -59.0064)
    line L457 (6.8059, -59.0064) -> (6.8043, -58.9606)
    line L458 (6.8043, -58.9606) -> (6.7996, -58.9168)
    line L459 (6.7996, -58.9168) -> (6.7917, -58.8749)
    line L460 (6.7917, -58.8749) -> (6.7806, -58.835)
    line L461 (6.7806, -58.835) -> (6.7664, -58.7971)
    line L462 (6.7664, -58.7971) -> (6.749, -58.7611)
    line L463 (6.749, -58.7611) -> (6.7284, -58.7271)
    line L464 (6.7284, -58.7271) -> (6.7047, -58.6951)
    line L465 (6.7047, -58.6951) -> (6.6779, -58.665)
    line L466 (6.6779, -58.665) -> (6.6478, -58.637)
    line L467 (6.6478, -58.637) -> (6.6148, -58.6112)
    line L468 (6.6148, -58.6112) -> (6.579, -58.5882)
    line L469 (6.579, -58.5882) -> (6.5403, -58.5679)
    line L470 (6.5403, -58.5679) -> (6.4988, -58.5503)
    line L471 (6.4988, -58.5503) -> (6.4544, -58.5354)
    line L472 (6.4544, -58.5354) -> (6.4072, -58.5232)
    line L473 (6.4072, -58.5232) -> (6.3572, -58.5137)
    line L474 (6.3572, -58.5137) -> (6.3043, -58.5069)
    line L475 (6.3043, -58.5069) -> (6.2487, -58.5029)
    line L476 (6.2487, -58.5029) -> (6.1901, -58.5015)
    line L477 (6.1901, -58.5015) -> (2.3151, -58.5015)
    line L478 (2.3151, -58.5015) -> (2.2536, -58.5029)
    line L479 (2.2536, -58.5029) -> (2.1952, -58.5071)
    line L480 (2.1952, -58.5071) -> (2.1401, -58.5141)
    line L481 (2.1401, -58.5141) -> (2.0882, -58.5238)
    line L482 (2.0882, -58.5238) -> (2.0396, -58.5364)
    line L483 (2.0396, -58.5364) -> (1.9942, -58.5517)
    line L484 (1.9942, -58.5517) -> (1.9521, -58.5699)
    line L485 (1.9521, -58.5699) -> (1.9132, -58.5908)
    line L486 (1.9132, -58.5908) -> (1.8775, -58.6146)
    line L487 (1.8775, -58.6146) -> (1.8451, -58.6411)
    line L488 (1.8451, -58.6411) -> (1.8159, -58.6698)
    line L489 (1.8159, -58.6698) -> (1.7897, -58.7003)
    line L490 (1.7897, -58.7003) -> (1.7666, -58.7326)
    line L491 (1.7666, -58.7326) -> (1.7466, -58.7665)
    line L492 (1.7466, -58.7665) -> (1.7297, -58.8022)
    line L493 (1.7297, -58.8022) -> (1.7158, -58.8396)
    line L494 (1.7158, -58.8396) -> (1.705, -58.8787)
    line L495 (1.705, -58.8787) -> (1.6974, -58.9195)
    line L496 (1.6974, -58.9195) -> (1.6927, -58.9621)
    line L497 (1.6927, -58.9621) -> (1.6912, -59.0064)
    line L498 (1.6912, -59.0064) -> (1.6928, -59.0507)
    line L499 (1.6928, -59.0507) -> (1.6974, -59.0932)
    line L500 (1.6974, -59.0932) -> (1.7052, -59.1339)
    line L501 (1.7052, -59.1339) -> (1.7162, -59.1729)
    line L502 (1.7162, -59.1729) -> (1.7302, -59.2101)
    line L503 (1.7302, -59.2101) -> (1.7474, -59.2455)
    line L504 (1.7474, -59.2455) -> (1.7676, -59.2792)
    line L505 (1.7676, -59.2792) -> (1.791, -59.3111)
    line L506 (1.791, -59.3111) -> (1.8175, -59.3413)
    line L507 (1.8175, -59.3413) -> (1.8472, -59.3697)
    line L508 (1.8472, -59.3697) -> (1.8799, -59.3958)
    line L509 (1.8799, -59.3958) -> (1.9158, -59.4192)
    line L510 (1.9158, -59.4192) -> (1.9548, -59.4398)
    line L511 (1.9548, -59.4398) -> (1.9969, -59.4577)
    line L512 (1.9969, -59.4577) -> (2.0422, -59.4728)
    line L513 (2.0422, -59.4728) -> (2.0905, -59.4852)
    line L514 (2.0905, -59.4852) -> (2.142, -59.4948)
    line L515 (2.142, -59.4948) -> (2.1966, -59.5017)
    line L516 (2.1966, -59.5017) -> (2.2543, -59.5058)
    line L517 (2.2543, -59.5058) -> (2.3151, -59.5072)
    line L518 (2.3151, -59.5072) -> (3.6451, -59.5072)
    line L519 (3.6451, -59.5072) -> (3.6451, -63.8789)
    line L520 (3.6451, -63.8789) -> (3.6468, -63.9525)
    line L521 (3.6468, -63.9525) -> (3.6519, -64.0222)
    line L522 (3.6519, -64.0222) -> (3.6603, -64.0879)
    line L523 (3.6603, -64.0879) -> (3.672, -64.1498)
    line L524 (3.672, -64.1498) -> (3.6872, -64.2078)
    line L525 (3.6872, -64.2078) -> (3.7057, -64.2619)
    line L526 (3.7057, -64.2619) -> (3.7276, -64.3121)
    line L527 (3.7276, -64.3121) -> (3.7528, -64.3584)
    line L528 (3.7528, -64.3584) -> (3.7814, -64.4007)
    line L529 (3.7814, -64.4007) -> (3.8134, -64.4392)
    line L530 (3.8134, -64.4392) -> (3.8481, -64.4739)
    line L531 (3.8481, -64.4739) -> (3.8847, -64.505)
    line L532 (3.8847, -64.505) -> (3.9233, -64.5324)
    line L533 (3.9233, -64.5324) -> (3.9638, -64.5561)
    line L534 (3.9638, -64.5561) -> (4.0063, -64.5762)
    line L535 (4.0063, -64.5762) -> (4.0508, -64.5926)
    line L536 (4.0508, -64.5926) -> (4.0973, -64.6055)
    line L537 (4.0973, -64.6055) -> (4.1458, -64.6146)
    line L538 (4.1458, -64.6146) -> (4.1962, -64.62)
    line L539 (4.1962, -64.62) -> (4.2485, -64.6219)
    line L540 (4.2485, -64.6219) -> (4.3017, -64.62)
    line L541 (4.3017, -64.62) -> (4.3529, -64.6145)
    line L542 (4.3529, -64.6145) -> (4.402, -64.6053)
    line L543 (4.402, -64.6053) -> (4.4492, -64.5923)
    line L544 (4.4492, -64.5923) -> (4.4943, -64.5757)
    line L545 (4.4943, -64.5757) -> (4.5374, -64.5554)
    line L546 (4.5374, -64.5554) -> (4.5785, -64.5314)
    line L547 (4.5785, -64.5314) -> (4.6176, -64.5037)
    line L548 (4.6176, -64.5037) -> (4.6547, -64.4723)
    line L549 (4.6547, -64.4723) -> (4.6898, -64.4372)
    line L550 (4.6898, -64.4372) -> (4.7222, -64.3983)
    line L551 (4.7222, -64.3983) -> (4.7511, -64.3557)
    line L552 (4.7511, -64.3557) -> (4.7767, -64.3093)
    line L553 (4.7767, -64.3093) -> (4.7988, -64.2592)
    line L554 (4.7988, -64.2592) -> (4.8176, -64.2052)
    line L555 (4.8176, -64.2052) -> (4.8329, -64.1475)
    line L556 (4.8329, -64.1475) -> (4.8448, -64.086)
    line L557 (4.8448, -64.086) -> (4.8533, -64.0208)
    line L558 (4.8533, -64.0208) -> (4.8585, -63.9517)
    line L559 (4.8585, -63.9517) -> (4.8602, -63.8789)
    line L560 (10.6013, -63.3934) -> (10.567, -63.4272)
    line L561 (10.567, -63.4272) -> (10.5305, -63.4597)
    line L562 (10.5305, -63.4597) -> (10.4919, -63.4908)
    line L563 (10.4919, -63.4908) -> (10.4511, -63.5206)
    line L564 (10.4511, -63.5206) -> (10.4081, -63.549)
    line L565 (10.4081, -63.549) -> (10.3629, -63.5761)
    line L566 (10.3629, -63.5761) -> (10.3156, -63.6018)
    line L567 (10.3156, -63.6018) -> (10.2656, -63.6256)
    line L568 (10.2656, -63.6256) -> (10.2126, -63.6469)
    line L569 (10.2126, -63.6469) -> (10.1566, -63.6657)
    line L570 (10.1566, -63.6657) -> (10.0975, -63.6819)
    line L571 (10.0975, -63.6819) -> (10.0354, -63.6957)
    line L572 (10.0354, -63.6957) -> (9.9703, -63.707)
    line L573 (9.9703, -63.707) -> (9.9021, -63.7157)
    line L574 (9.9021, -63.7157) -> (9.8308, -63.722)
    line L575 (9.8308, -63.722) -> (9.7566, -63.7258)
    line L576 (9.7566, -63.7258) -> (9.6793, -63.727)
    line L577 (9.6793, -63.727) -> (9.573, -63.7245)
    line L578 (9.573, -63.7245) -> (9.4707, -63.7169)
    line L579 (9.4707, -63.7169) -> (9.3725, -63.7043)
    line L580 (9.3725, -63.7043) -> (9.2783, -63.6866)
    line L581 (9.2783, -63.6866) -> (9.1883, -63.6639)
    line L582 (9.1883, -63.6639) -> (9.1022, -63.6361)
    line L583 (9.1022, -63.6361) -> (9.0203, -63.6033)
    line L584 (9.0203, -63.6033) -> (8.9424, -63.5654)
    line L585 (8.9424, -63.5654) -> (8.8686, -63.5225)
    line L586 (8.8686, -63.5225) -> (8.7988, -63.4746)
    line L587 (8.7988, -63.4746) -> (8.7345, -63.4228)
    line L588 (8.7345, -63.4228) -> (8.6769, -63.3686)
    line L589 (8.6769, -63.3686) -> (8.6261, -63.3118)
    line L590 (8.6261, -63.3118) -> (8.5821, -63.2526)
    line L591 (8.5821, -63.2526) -> (8.5448, -63.1908)
    line L592 (8.5448, -63.1908) -> (8.5143, -63.1266)
    line L593 (8.5143, -63.1266) -> (8.4906, -63.0598)
    line L594 (8.4906, -63.0598) -> (8.4737, -62.9905)
    line L595 (8.4737, -62.9905) -> (8.4635, -62.9187)
    line L596 (8.4635, -62.9187) -> (8.4602, -62.8445)
    line L597 (8.4602, -62.8445) -> (8.462, -62.7857)
    line L598 (8.462, -62.7857) -> (8.4674, -62.7291)
    line L599 (8.4674, -62.7291) -> (8.4766, -62.6748)
    line L600 (8.4766, -62.6748) -> (8.4894, -62.6228)
    line L601 (8.4894, -62.6228) -> (8.5058, -62.573)
    line L602 (8.5058, -62.573) -> (8.5259, -62.5255)
    line L603 (8.5259, -62.5255) -> (8.5497, -62.4803)
    line L604 (8.5497, -62.4803) -> (8.5771, -62.4373)
    line L605 (8.5771, -62.4373) -> (8.6081, -62.3965)
    line L606 (8.6081, -62.3965) -> (8.6428, -62.358)
    line L607 (8.6428, -62.358) -> (8.6804, -62.3216)
    line L608 (8.6804, -62.3216) -> (8.7202, -62.2869)
    line L609 (8.7202, -62.2869) -> (8.762, -62.2539)
    line L610 (8.762, -62.2539) -> (8.806, -62.2227)
    line L611 (8.806, -62.2227) -> (8.8522, -62.1933)
    line L612 (8.8522, -62.1933) -> (8.9004, -62.1657)
    line L613 (8.9004, -62.1657) -> (8.9508, -62.1398)
    line L614 (8.9508, -62.1398) -> (9.0034, -62.1157)
    line L615 (9.0034, -62.1157) -> (9.0581, -62.0933)
    line L616 (9.0581, -62.0933) -> (9.1149, -62.0727)
    line L617 (9.1149, -62.0727) -> (9.1747, -62.0529)
    line L618 (9.1747, -62.0529) -> (9.2384, -62.0328)
    line L619 (9.2384, -62.0328) -> (9.3061, -62.0125)
    line L620 (9.3061, -62.0125) -> (9.3776, -61.992)
    line L621 (9.3776, -61.992) -> (9.453, -61.9711)
    line L622 (9.453, -61.9711) -> (9.5323, -61.9501)
    line L623 (9.5323, -61.9501) -> (9.6156, -61.9288)
    line L624 (9.6156, -61.9288) -> (9.7027, -61.9073)
    line L625 (9.7027, -61.9073) -> (9.7937, -61.8854)
    line L626 (9.7937, -61.8854) -> (9.8886, -61.8634)
    line L627 (9.8886, -61.8634) -> (10.0162, -61.8325)
    line L628 (10.0162, -61.8325) -> (10.1396, -61.8006)
    line L629 (10.1396, -61.8006) -> (10.2588, -61.7677)
    line L630 (10.2588, -61.7677) -> (10.3737, -61.7337)
    line L631 (10.3737, -61.7337) -> (10.4844, -61.6987)
    line L632 (10.4844, -61.6987) -> (10.5908, -61.6627)
    line L633 (10.5908, -61.6627) -> (10.6931, -61.6256)
    line L634 (10.6931, -61.6256) -> (10.7911, -61.5876)
    line L635 (10.7911, -61.5876) -> (10.8848, -61.5485)
    line L636 (10.8848, -61.5485) -> (10.9744, -61.5083)
    line L637 (10.9744, -61.5083) -> (11.06, -61.4662)
    line L638 (11.06, -61.4662) -> (11.142, -61.4211)
    line L639 (11.142, -61.4211) -> (11.2204, -61.3731)
    line L640 (11.2204, -61.3731) -> (11.2952, -61.3221)
    line L641 (11.2952, -61.3221) -> (11.3664, -61.2682)
    line L642 (11.3664, -61.2682) -> (11.434, -61.2113)
    line L643 (11.434, -61.2113) -> (11.4979, -61.1515)
    line L644 (11.4979, -61.1515) -> (11.5583, -61.0887)
    line L645 (11.5583, -61.0887) -> (11.615, -61.0229)
    line L646 (11.615, -61.0229) -> (11.6681, -60.9542)
    line L647 (11.6681, -60.9542) -> (11.7169, -60.8823)
    line L648 (11.7169, -60.8823) -> (11.7605, -60.807)
    line L649 (11.7605, -60.807) -> (11.799, -60.7283)
    line L650 (11.799, -60.7283) -> (11.8323, -60.6461)
    line L651 (11.8323, -60.6461) -> (11.8605, -60.5606)
    line L652 (11.8605, -60.5606) -> (11.8836, -60.4717)
    line L653 (11.8836, -60.4717) -> (11.9016, -60.3793)
    line L654 (11.9016, -60.3793) -> (11.9144, -60.2836)
    line L655 (11.9144, -60.2836) -> (11.9221, -60.1844)
    line L656 (11.9221, -60.1844) -> (11.9247, -60.0819)
    line L657 (11.9247, -60.0819) -> (11.922, -59.9836)
    line L658 (11.922, -59.9836) -> (11.9138, -59.8876)
    line L659 (11.9138, -59.8876) -> (11.9003, -59.7938)
    line L660 (11.9003, -59.7938) -> (11.8813, -59.7023)
    line L661 (11.8813, -59.7023) -> (11.8569, -59.6129)
    line L662 (11.8569, -59.6129) -> (11.8271, -59.5257)
    line L663 (11.8271, -59.5257) -> (11.7919, -59.4408)
    line L664 (11.7919, -59.4408) -> (11.7513, -59.3581)
    line L665 (11.7513, -59.3581) -> (11.7052, -59.2776)
    line L666 (11.7052, -59.2776) -> (11.6537, -59.1993)
    line L667 (11.6537, -59.1993) -> (11.5971, -59.1239)
    line L668 (11.5971, -59.1239) -> (11.5357, -59.0521)
    line L669 (11.5357, -59.0521) -> (11.4694, -58.9839)
    line L670 (11.4694, -58.9839) -> (11.3983, -58.9192)
    line L671 (11.3983, -58.9192) -> (11.3223, -58.8581)
    line L672 (11.3223, -58.8581) -> (11.2415, -58.8006)
    line L673 (11.2415, -58.8006) -> (11.1558, -58.7466)
    line L674 (11.1558, -58.7466) -> (11.0653, -58.6962)
    line L675 (11.0653, -58.6962) -> (10.9699, -58.6494)
    line L676 (10.9699, -58.6494) -> (10.8697, -58.6062)
    line L677 (10.8697, -58.6062) -> (10.7653, -58.5668)
    line L678 (10.7653, -58.5668) -> (10.6572, -58.5316)
    line L679 (10.6572, -58.5316) -> (10.5456, -58.5005)
    line L680 (10.5456, -58.5005) -> (10.4303, -58.4735)
    line L681 (10.4303, -58.4735) -> (10.3114, -58.4507)
    line L682 (10.3114, -58.4507) -> (10.189, -58.432)
    line L683 (10.189, -58.432) -> (10.0628, -58.4175)
    line L684 (10.0628, -58.4175) -> (9.9331, -58.4072)
    line L685 (9.9331, -58.4072) -> (9.7998, -58.401)
    line L686 (9.7998, -58.401) -> (9.6629, -58.3989)
    line L687 (9.6629, -58.3989) -> (9.5535, -58.4003)
    line L688 (9.5535, -58.4003) -> (9.4472, -58.4044)
    line L689 (9.4472, -58.4044) -> (9.3439, -58.4113)
    line L690 (9.3439, -58.4113) -> (9.2435, -58.4209)
    line L691 (9.2435, -58.4209) -> (9.1462, -58.4333)
    line L692 (9.1462, -58.4333) -> (9.0518, -58.4484)
    line L693 (9.0518, -58.4484) -> (8.9605, -58.4663)
    line L694 (8.9605, -58.4663) -> (8.8721, -58.4869)
    line L695 (8.8721, -58.4869) -> (8.7868, -58.5103)
    line L696 (8.7868, -58.5103) -> (8.7044, -58.5364)
    line L697 (8.7044, -58.5364) -> (8.6249, -58.5648)
    line L698 (8.6249, -58.5648) -> (8.5482, -58.595)
    line L699 (8.5482, -58.595) -> (8.4742, -58.627)
    line L700 (8.4742, -58.627) -> (8.4029, -58.6609)
    line L701 (8.4029, -58.6609) -> (8.3344, -58.6965)
    line L702 (8.3344, -58.6965) -> (8.2687, -58.7339)
    line L703 (8.2687, -58.7339) -> (8.2057, -58.7732)
    line L704 (8.2057, -58.7732) -> (8.1455, -58.8142)
    line L705 (8.1455, -58.8142) -> (8.088, -58.8571)
    line L706 (8.088, -58.8571) -> (8.0332, -58.9017)
    line L707 (8.0332, -58.9017) -> (7.9813, -58.9475)
    line L708 (7.9813, -58.9475) -> (7.9323, -58.9937)
    line L709 (7.9323, -58.9937) -> (7.8861, -59.0405)
    line L710 (7.8861, -59.0405) -> (7.8428, -59.0876)
    line L711 (7.8428, -59.0876) -> (7.8023, -59.1352)
    line L712 (7.8023, -59.1352) -> (7.7648, -59.1833)
    line L713 (7.7648, -59.1833) -> (7.7301, -59.2317)
    line L714 (7.7301, -59.2317) -> (7.6983, -59.2807)
    line L715 (7.6983, -59.2807) -> (7.6693, -59.3301)
    line L716 (7.6693, -59.3301) -> (7.6433, -59.3799)
    line L717 (7.6433, -59.3799) -> (7.6199, -59.4299)
    line L718 (7.6199, -59.4299) -> (7.5989, -59.4796)
    line L719 (7.5989, -59.4796) -> (7.5805, -59.5291)
    line L720 (7.5805, -59.5291) -> (7.5645, -59.5783)
    line L721 (7.5645, -59.5783) -> (7.5509, -59.6273)
    line L722 (7.5509, -59.6273) -> (7.5398, -59.676)
    line L723 (7.5398, -59.676) -> (7.5312, -59.7245)
    line L724 (7.5312, -59.7245) -> (7.5251, -59.7727)
    line L725 (7.5251, -59.7727) -> (7.5214, -59.8207)
    line L726 (7.5214, -59.8207) -> (7.5201, -59.8684)
    line L727 (7.5201, -59.8684) -> (7.5217, -59.9115)
    line L728 (7.5217, -59.9115) -> (7.5263, -59.9537)
    line L729 (7.5263, -59.9537) -> (7.534, -59.9951)
    line L730 (7.534, -59.9951) -> (7.5448, -60.0356)
    line L731 (7.5448, -60.0356) -> (7.5586, -60.0752)
    line L732 (7.5586, -60.0752) -> (7.5755, -60.114)
    line L733 (7.5755, -60.114) -> (7.5956, -60.1519)
    line L734 (7.5956, -60.1519) -> (7.6186, -60.1889)
    line L735 (7.6186, -60.1889) -> (7.6448, -60.2251)
    line L736 (7.6448, -60.2251) -> (7.6741, -60.2605)
    line L737 (7.6741, -60.2605) -> (7.7056, -60.2936)
    line L738 (7.7056, -60.2936) -> (7.7387, -60.3233)
    line L739 (7.7387, -60.3233) -> (7.7733, -60.3494)
    line L740 (7.7733, -60.3494) -> (7.8094, -60.3721)
    line L741 (7.8094, -60.3721) -> (7.847, -60.3913)
    line L742 (7.847, -60.3913) -> (7.8861, -60.407)
    line L743 (7.8861, -60.407) -> (7.9268, -60.4192)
